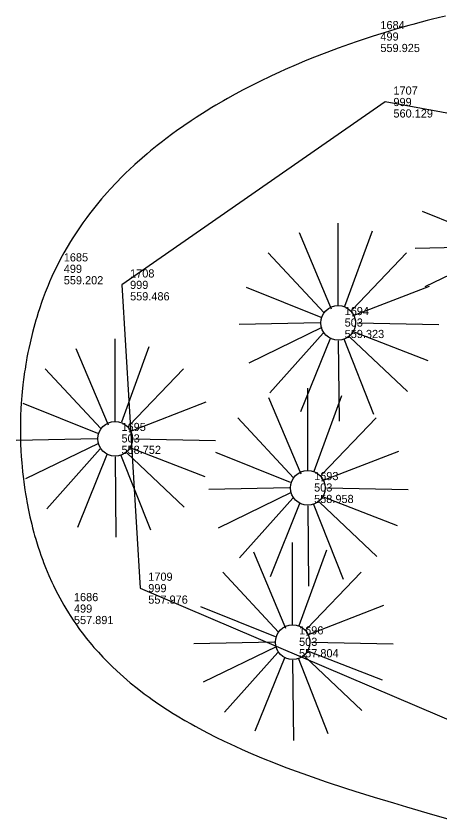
# Model space of a CAD drawing. Extents: x 5447 to 709667, y 4528 to 375505.
# Drawn here: x 707475.76 to 707488.72, y 374441.94 to 374466.6 of the extents above; entities that cross this region are included whole.
import ezdxf

# ---------------------------------------------------------------- set-up
doc = ezdxf.new("R2010")
doc.units = 0
for name, color, linetype in [('SV_BKLN_BKLN', 7, 'Continuous'), ('SV_NODES_ACTIVE_POINT', 7, 'Continuous'), ('SV_NODES_DESCRIPTION', 7, 'Continuous'), ('SV_NODES_ELEVATION', 7, 'Continuous'), ('SV_NODES_PT_NUMBER', 7, 'Continuous'), ('SV_TREE_TREEVEG', 7, 'Continuous')]:
    doc.layers.add(name, color=color, linetype=linetype)

msp = doc.modelspace()

# ---------------------------------------------------------------- linework, layer by layer
at = {"layer": 'SV_BKLN_BKLN'}
msp.add_lwpolyline([(707508.404, 374451.469), (707499.614, 374461.672), (707487.053, 374463.971), (707478.999, 374458.382), (707479.555, 374449.113), (707493.632, 374443.114), (707504.109, 374443.195), (707508.101, 374447.975), (707508.404, 374451.469)], dxfattribs=at)
at = {"layer": 'SV_NODES_ACTIVE_POINT'}
for p, q in [((707486.654, 374465.972), (707486.654, 374465.972)), ((707487.053, 374463.971), (707487.053, 374463.971)), ((707476.971, 374458.873), (707476.971, 374458.873)), ((707478.999, 374458.382), (707478.999, 374458.382)), ((707479.555, 374449.113), (707479.555, 374449.113)), ((707477.282, 374448.489), (707477.282, 374448.489)), ((707488.499, 374442.197), (707488.499, 374442.197))]:
    msp.add_line(p, q, dxfattribs=at)
at = {"layer": 'SV_TREE_TREEVEG'}
for p, q in [((707490.472, 374459.71), (707488.188, 374460.624)), ((707485.615, 374457.748), (707485.615, 374460.27)), ((707484.415, 374459.981), (707485.4, 374457.65)), ((707486.648, 374460.028), (707485.807, 374457.722)), ((707483.476, 374459.357), (707485.183, 374457.53)), ((707486.049, 374457.628), (707487.706, 374459.357)), ((707490.446, 374459.543), (707487.971, 374459.496)), ((707490.494, 374459.399), (707488.261, 374458.318)), ((707485.089, 374457.385), (707482.805, 374458.299)), ((707486.049, 374457.436), (707488.402, 374458.346)), ((707485.063, 374457.218), (707482.588, 374457.171)), ((707486.191, 374457.218), (707488.689, 374457.171)), ((707485.111, 374457.074), (707482.878, 374455.993)), ((707485.158, 374456.907), (707483.526, 374455.08)), ((707486.071, 374456.954), (707488.355, 374456.066)), ((707478.79, 374454.207), (707478.79, 374456.729)), ((707485.375, 374456.762), (707484.462, 374454.503)), ((707485.615, 374456.667), (707485.64, 374454.214)), ((707485.781, 374456.737), (707486.695, 374454.431)), ((707485.974, 374456.787), (707487.728, 374455.127)), ((707477.59, 374456.44), (707478.575, 374454.109)), ((707479.823, 374456.487), (707478.982, 374454.181)), ((707476.651, 374455.816), (707478.358, 374453.989)), ((707479.224, 374454.087), (707480.881, 374455.816)), ((707484.681, 374452.706), (707484.681, 374455.228)), ((707483.481, 374454.939), (707484.466, 374452.608)), ((707485.714, 374454.986), (707484.873, 374452.68)), ((707478.264, 374453.844), (707475.98, 374454.758)), ((707479.224, 374453.895), (707481.577, 374454.805)), ((707482.542, 374454.315), (707484.249, 374452.488)), ((707485.115, 374452.586), (707486.772, 374454.315)), ((707478.238, 374453.677), (707475.763, 374453.63)), ((707479.366, 374453.677), (707481.864, 374453.63)), ((707478.286, 374453.533), (707476.053, 374452.452)), ((707478.333, 374453.366), (707476.701, 374451.539)), ((707478.55, 374453.221), (707477.637, 374450.962)), ((707478.956, 374453.196), (707479.87, 374450.89)), ((707479.149, 374453.246), (707480.903, 374451.586)), ((707479.246, 374453.413), (707481.53, 374452.525)), ((707484.155, 374452.343), (707481.871, 374453.257)), ((707485.115, 374452.394), (707487.468, 374453.304)), ((707478.79, 374453.126), (707478.815, 374450.673)), ((707484.129, 374452.176), (707481.654, 374452.129)), ((707484.177, 374452.032), (707481.944, 374450.951)), ((707485.257, 374452.176), (707487.755, 374452.129)), ((707484.224, 374451.865), (707482.592, 374450.038)), ((707484.441, 374451.72), (707483.528, 374449.461)), ((707485.04, 374451.745), (707486.794, 374450.085)), ((707485.137, 374451.912), (707487.421, 374451.024)), ((707484.681, 374451.625), (707484.706, 374449.172)), ((707484.847, 374451.695), (707485.761, 374449.389)), ((707484.221, 374447.99), (707484.221, 374450.512)), ((707483.021, 374450.223), (707484.006, 374447.892)), ((707485.254, 374450.27), (707484.413, 374447.964)), ((707482.082, 374449.599), (707483.789, 374447.772)), ((707484.655, 374447.87), (707486.312, 374449.599)), ((707483.695, 374447.627), (707481.411, 374448.541)), ((707484.655, 374447.678), (707487.008, 374448.588)), ((707483.669, 374447.46), (707481.194, 374447.413)), ((707483.717, 374447.316), (707481.484, 374446.235)), ((707484.797, 374447.46), (707487.295, 374447.413)), ((707483.764, 374447.149), (707482.132, 374445.322)), ((707484.58, 374447.029), (707486.334, 374445.369)), ((707484.677, 374447.196), (707486.961, 374446.308)), ((707483.981, 374447.004), (707483.068, 374444.745)), ((707484.221, 374446.909), (707484.246, 374444.456)), ((707484.387, 374446.979), (707485.301, 374444.673))]:
    msp.add_line(p, q, dxfattribs=at)
msp.add_lwpolyline([(707488.897, 374466.595), (707488.711, 374466.551), (707488.461, 374466.49), (707488.337, 374466.458), (707488.15, 374466.41), (707487.9, 374466.343), (707487.776, 374466.309), (707487.402, 374466.202), (707487.153, 374466.128), (707486.82, 374466.025), (707486.654, 374465.972), (707486.192, 374465.82), (707485.961, 374465.74), (707485.616, 374465.617), (707485.271, 374465.488), (707485.099, 374465.423), (707484.756, 374465.287), (707484.585, 374465.217), (707484.33, 374465.11), (707483.992, 374464.962), (707483.823, 374464.887), (707483.572, 374464.771), (707483.198, 374464.591), (707482.869, 374464.425), (707482.706, 374464.34), (707482.464, 374464.21), (707482.223, 374464.077), (707482.104, 374464.009), (707481.867, 374463.871), (707481.749, 374463.801), (707481.575, 374463.693), (707481.267, 374463.498), (707481.116, 374463.399), (707480.891, 374463.246), (707480.67, 374463.09), (707480.56, 374463.011), (707480.344, 374462.85), (707480.237, 374462.768), (707480.078, 374462.643), (707479.87, 374462.474), (707479.767, 374462.388), (707479.615, 374462.257), (707479.391, 374462.057), (707479.218, 374461.896), (707479.132, 374461.814), (707479.006, 374461.69), (707478.82, 374461.5), (707478.639, 374461.307), (707478.55, 374461.209), (707478.376, 374461.01), (707478.291, 374460.909), (707478.166, 374460.756), (707478.003, 374460.548), (707477.924, 374460.443), (707477.808, 374460.282), (707477.639, 374460.038), (707477.495, 374459.816), (707477.425, 374459.704), (707477.323, 374459.534), (707477.224, 374459.361), (707477.176, 374459.274), (707477.083, 374459.097), (707477.037, 374459.008), (707476.971, 374458.873), (707476.859, 374458.636), (707476.789, 374458.475), (707476.743, 374458.367), (707476.655, 374458.148), (707476.593, 374457.983), (707476.553, 374457.872), (707476.476, 374457.648), (707476.439, 374457.535), (707476.392, 374457.383), (707476.369, 374457.307), (707476.304, 374457.078), (707476.264, 374456.923), (707476.189, 374456.613), (707476.15, 374456.436), (707476.126, 374456.319), (707476.096, 374456.161), (707476.082, 374456.082), (707476.061, 374455.963), (707476.036, 374455.804), (707476.024, 374455.724), (707475.991, 374455.485), (707475.972, 374455.324), (707475.949, 374455.11), (707475.94, 374455.003), (707475.921, 374454.761), (707475.912, 374454.6), (707475.902, 374454.384), (707475.899, 374454.277), (707475.894, 374453.954), (707475.895, 374453.81), (707475.898, 374453.619), (707475.901, 374453.523), (707475.91, 374453.308), (707475.919, 374453.148), (707475.935, 374452.934), (707475.944, 374452.827), (707475.96, 374452.668), (707475.984, 374452.456), (707475.997, 374452.35), (707476.031, 374452.113), (707476.049, 374451.995), (707476.076, 374451.838), (707476.09, 374451.76), (707476.151, 374451.45), (707476.185, 374451.296), (707476.24, 374451.066), (707476.269, 374450.952), (707476.309, 374450.801), (707476.33, 374450.726), (707476.363, 374450.614), (707476.408, 374450.465), (707476.432, 374450.391), (707476.486, 374450.226), (707476.524, 374450.117), (707476.577, 374449.972), (707476.604, 374449.9), (707476.666, 374449.74), (707476.765, 374449.503), (707476.858, 374449.295), (707476.906, 374449.193), (707476.98, 374449.041), (707477.096, 374448.817), (707477.219, 374448.597), (707477.282, 374448.489), (707477.362, 374448.358), (707477.417, 374448.272), (707477.528, 374448.103), (707477.586, 374448.019), (707477.704, 374447.854), (707477.825, 374447.693), (707477.908, 374447.587), (707478.078, 374447.379), (707478.144, 374447.303), (707478.278, 374447.153), (707478.415, 374447.005), (707478.508, 374446.909), (707478.699, 374446.719), (707478.846, 374446.581), (707478.946, 374446.49), (707479.15, 374446.312), (707479.254, 374446.224), (707479.465, 374446.054), (707479.682, 374445.887), (707479.829, 374445.779), (707479.929, 374445.708), (707480.13, 374445.568), (707480.391, 374445.396), (707480.568, 374445.284), (707480.687, 374445.211), (707480.928, 374445.067), (707481.112, 374444.962), (707481.236, 374444.893), (707481.487, 374444.757), (707481.614, 374444.691), (707481.87, 374444.561), (707482.13, 374444.434), (707482.305, 374444.351), (707482.66, 374444.19), (707482.861, 374444.101), (707483.27, 374443.929), (707483.685, 374443.762), (707483.965, 374443.654), (707484.152, 374443.584), (707484.531, 374443.445), (707484.961, 374443.294), (707485.249, 374443.196), (707485.832, 374443.004), (707486.125, 374442.91), (707486.715, 374442.726), (707487.308, 374442.547), (707487.705, 374442.429), (707488.499, 374442.197), (707489.395, 374441.939)], dxfattribs=at)
for centre in [(707485.615, 374457.218), (707478.79, 374453.677), (707484.681, 374452.176), (707484.221, 374447.46)]:
    msp.add_circle(centre, 0.53, dxfattribs=at)

# ---------------------------------------------------------------- texts
at = {"layer": 'SV_NODES_DESCRIPTION'}
for s, p in [('499', (707486.904, 374465.847)), ('999', (707487.303, 374463.846)), ('499', (707477.221, 374458.748)), ('999', (707479.249, 374458.257)), ('503', (707485.811, 374457.106)), ('503', (707478.986, 374453.565)), ('503', (707484.877, 374452.064)), ('999', (707479.805, 374448.988)), ('499', (707477.532, 374448.364)), ('503', (707484.417, 374447.348))]:
    msp.add_text(s, height=0.25, dxfattribs=at).set_placement(p)
at = {"layer": 'SV_NODES_ELEVATION'}
for s, p in [('559.925', (707486.904, 374465.497)), ('560.129', (707487.303, 374463.496)), ('559.202', (707477.221, 374458.398)), ('559.486', (707479.249, 374457.907)), ('559.323', (707485.811, 374456.756)), ('558.752', (707478.986, 374453.215)), ('558.958', (707484.877, 374451.714)), ('557.976', (707479.805, 374448.638)), ('557.891', (707477.532, 374448.014)), ('557.804', (707484.417, 374446.998))]:
    msp.add_text(s, height=0.25, dxfattribs=at).set_placement(p)
at = {"layer": 'SV_NODES_PT_NUMBER'}
for s, p in [('1684', (707486.904, 374466.197)), ('1707', (707487.303, 374464.196)), ('1685', (707477.221, 374459.098)), ('1708', (707479.249, 374458.607)), ('1694', (707485.811, 374457.456)), ('1695', (707478.986, 374453.915)), ('1693', (707484.877, 374452.414)), ('1709', (707479.805, 374449.338)), ('1686', (707477.532, 374448.714)), ('1696', (707484.417, 374447.698))]:
    msp.add_text(s, height=0.25, dxfattribs=at).set_placement(p)

doc.saveas('drawing.dxf')
